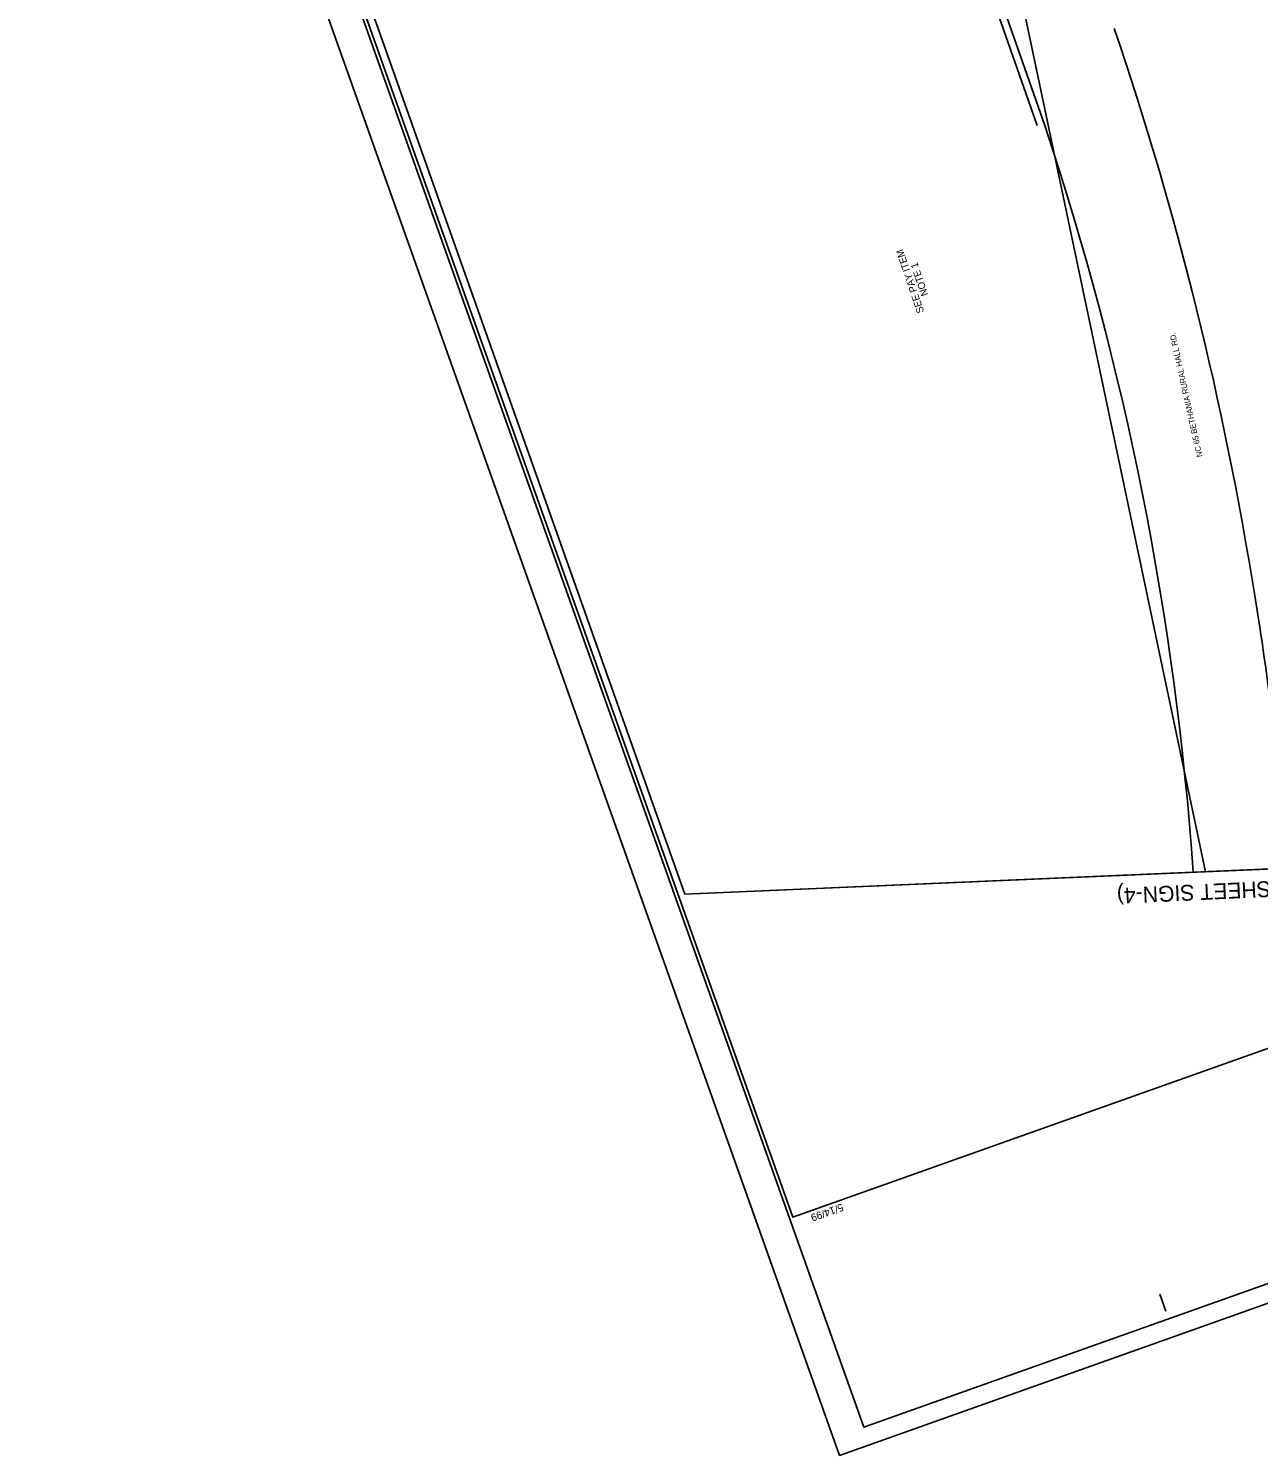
# Model space of a CAD drawing. Extents: x 1615843 to 1617444, y 901966 to 903921.
# Drawn here: x 1615843 to 1616698, y 901966 to 902958 of the extents above; entities that cross this region are included whole.
import ezdxf

# ---------------------------------------------------------------- set-up
doc = ezdxf.new("R2010")
doc.units = 0
for name, color, linetype in [('CTL Primary Horizontal and Vertical CELL', 7, 'Continuous'), ('CTL Primary Horizontal and Vertical Cogo Number', 7, 'Continuous'), ('CTL Secondary Horizontal and Vertical CELL', 7, 'Continuous'), ('Default', 7, 'Continuous'), ('Exist DTM Crownline Cogo Number', 7, 'Continuous'), ('Exist DTM Crownline Cogo Point CELL', 7, 'Continuous'), ('Exist DTM Regular Point CELL', 7, 'Continuous'), ('Exist DTM Regular Point Cogo Number', 7, 'Continuous'), ('Exist Roads Curbs Cogo Number', 7, 'Continuous'), ('Exist Roads Curbs Cogo Point CELL', 7, 'Continuous')]:
    doc.layers.add(name, color=color, linetype=linetype)

msp = doc.modelspace()

# ---------------------------------------------------------------- linework, layer by layer
at = {"layer": 'CTL Primary Horizontal and Vertical CELL'}
msp.add_lwpolyline([(1615865.68, 903555.66), (1616423.91, 901985.43), (1617418.05, 902338.86), (1616859.83, 903909.09)], close=True, dxfattribs=at)
at = {"layer": 'CTL Primary Horizontal and Vertical Cogo Number'}
msp.add_lwpolyline([(1615843.02, 903552.38), (1616407.11, 901965.67), (1617443.56, 902334.13), (1616879.47, 903920.85)], close=True, dxfattribs=at)
at = {"layer": 'CTL Secondary Horizontal and Vertical CELL'}
for p, q in [((1616374.39, 902132.33), (1616374.39, 902132.33)), ((1616634.11, 902066), (1616629.93, 902077.78))]:
    msp.add_line(p, q, dxfattribs=at)
msp.add_lwpolyline([(1615872.27, 903544.74), (1616374.72, 902131.39), (1617364.06, 902483.11), (1616861.61, 903896.45)], close=True, dxfattribs=at)
at = {"layer": 'Exist DTM Crownline Cogo Point CELL'}
msp.add_lwpolyline([(1616920.55, 902382.99), (1616299.46, 902356.07), (1615953.12, 903334.31), (1616369.18, 903520.6), (1616903.33, 903759.78), (1617120.19, 903154.34), (1617263.37, 902747.79), (1617083.45, 902390.05)], close=True, dxfattribs=at)
at = {"layer": 'Exist DTM Regular Point CELL'}
for p, q in [((1616415.34, 903541.28), (1616661.72, 902371.77)), ((1616698.46, 902547.52), (1616695.86, 902563.86))]:
    msp.add_line(p, q, dxfattribs=at)
msp.add_lwpolyline([(1616549.87, 902890.96), (1616367.91, 903409.77)], dxfattribs=at)
for centre, radius, start, end in [((1614325.74, 902186.35), 2400, 9.05, 18.76383), ((1614538.44, 902221.24), 2120, 4.06172, 18.41557), ((1615052.19, 902285.31), 1667.02, 3.05543, 9.05)]:
    msp.add_arc(centre, radius, start, end, dxfattribs=at)
at = {"layer": 'Exist DTM Regular Point Cogo Number'}
msp.add_lwpolyline([(1616544.59, 902890.91), (1616363.19, 903408.12)], dxfattribs=at)
at = {"layer": 'Exist Roads Curbs Cogo Point CELL'}
msp.add_line((1616299.46, 902356.07), (1617083.45, 902390.05), dxfattribs=at)

# ---------------------------------------------------------------- texts
at = {"layer": 'CTL Secondary Horizontal and Vertical CELL'}
msp.add_text('5/14/99', height=5.25, rotation=199.57069, dxfattribs=at).set_placement((1616408.64, 902141.06))
at = {"layer": 'Default'}
for s, p in [('SEE PAY ITEM', (1616465.99, 902761.3)), ('NOTE 1', (1616468.85, 902773.24))]:
    msp.add_text(s, height=5, rotation=108.77928, dxfattribs=at).set_placement(p)
at = {"layer": 'Exist DTM Crownline Cogo Number'}
msp.add_text('NC 65 BETHANIA RURAL HALL RD.', height=4, rotation=102.48627, dxfattribs=at).set_placement((1616659.6, 902660.68))
at = {"layer": 'Exist Roads Curbs Cogo Number'}
msp.add_text('MATCHLINE -L- STA. 38+00.00 (SEE SHEET SIGN-4)', height=11, rotation=182.66245, dxfattribs=at).set_placement((1616958.66, 902377.04))

doc.saveas('drawing.dxf')
